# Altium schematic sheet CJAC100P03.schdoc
size 127 x 101 mm
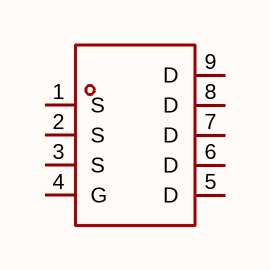
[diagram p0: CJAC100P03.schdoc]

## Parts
Q?  cjac100p03  [PDFN-8_L5.8-W4.9-P1.27-LS6.1-BL]  (value not drawn)

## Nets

Not connected (* = marked no-connect by the designer): Q? 1(S) 2(S) 3(S) 4(G) 5(D) 6(D) 7(D) 8(D) 9(D)

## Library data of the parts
Q? = cjac100p03: 数量:1个P沟道;漏源电压(Vdss):30V;连续漏极电流(Id):100A;导通电阻(RDS(on)):2.3mΩ@10V;耗散功率(Pd):-;阈值电压(Vgs(th)):1.2V;; Manufacturer: CJ(江苏长电/长晶); AddInBom: yes; ModelId: e4f86a8f30fa4f6d9bf0edb4447c4e78; ModelTransform: 196.85,238.189,0,0,0,0,-0.005,-3.265,0; Number: 1个P沟道; Drain to Source Voltage: 30V; Current - Continuous Drain(Id): 100A; Gate Threshold Voltage (Vgs(th)): 1.2V; Gate Charge(Qg): 210nC@10V; Input Capacitance(Ciss): 12nF; Reverse Transfer Capacitance (Crss@Vds): 750pF; Type: P沟道; Output Capacitance(Coss): 985pF; Vgs: ±20V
